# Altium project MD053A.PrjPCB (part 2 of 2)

## Sheet MD053A_POWER_AND_CONNECTORS.SchDoc
size 431 x 279 mm; Date: Not shown in title block; ApprovedBy: Not shown in title block; CheckedBy: Not shown in title block; Author: Not shown in title block; CompanyName: Not shown in title block; Engineer: Not shown in title block; Organization: Not shown in title block; Address1: Not shown in title block; Address2: Not shown in title block; Address3: Not shown in title block; Address4: Not shown in title block; DocumentNumber: 4; Revision: Use project parameter SCH_Rev; SheetNumber: 4; SheetTotal: 5; PageSetup: Record=PageOptions¦CenterHorizontal=True¦CenterVertical=True¦PrintScale=1.00¦XCorrection=1.00¦YCorrection=1.00¦PrintKind=0¦BorderSize=5000000¦LeftOffset=0¦BottomOffset=0¦Orientation=2¦PaperLength=1000¦PaperWidth=1000¦Scale=100¦PaperSource=15¦PrintQuality=600¦MediaType=1¦DitherType=10¦PaperKind=Letter¦PrintScaleMode=1
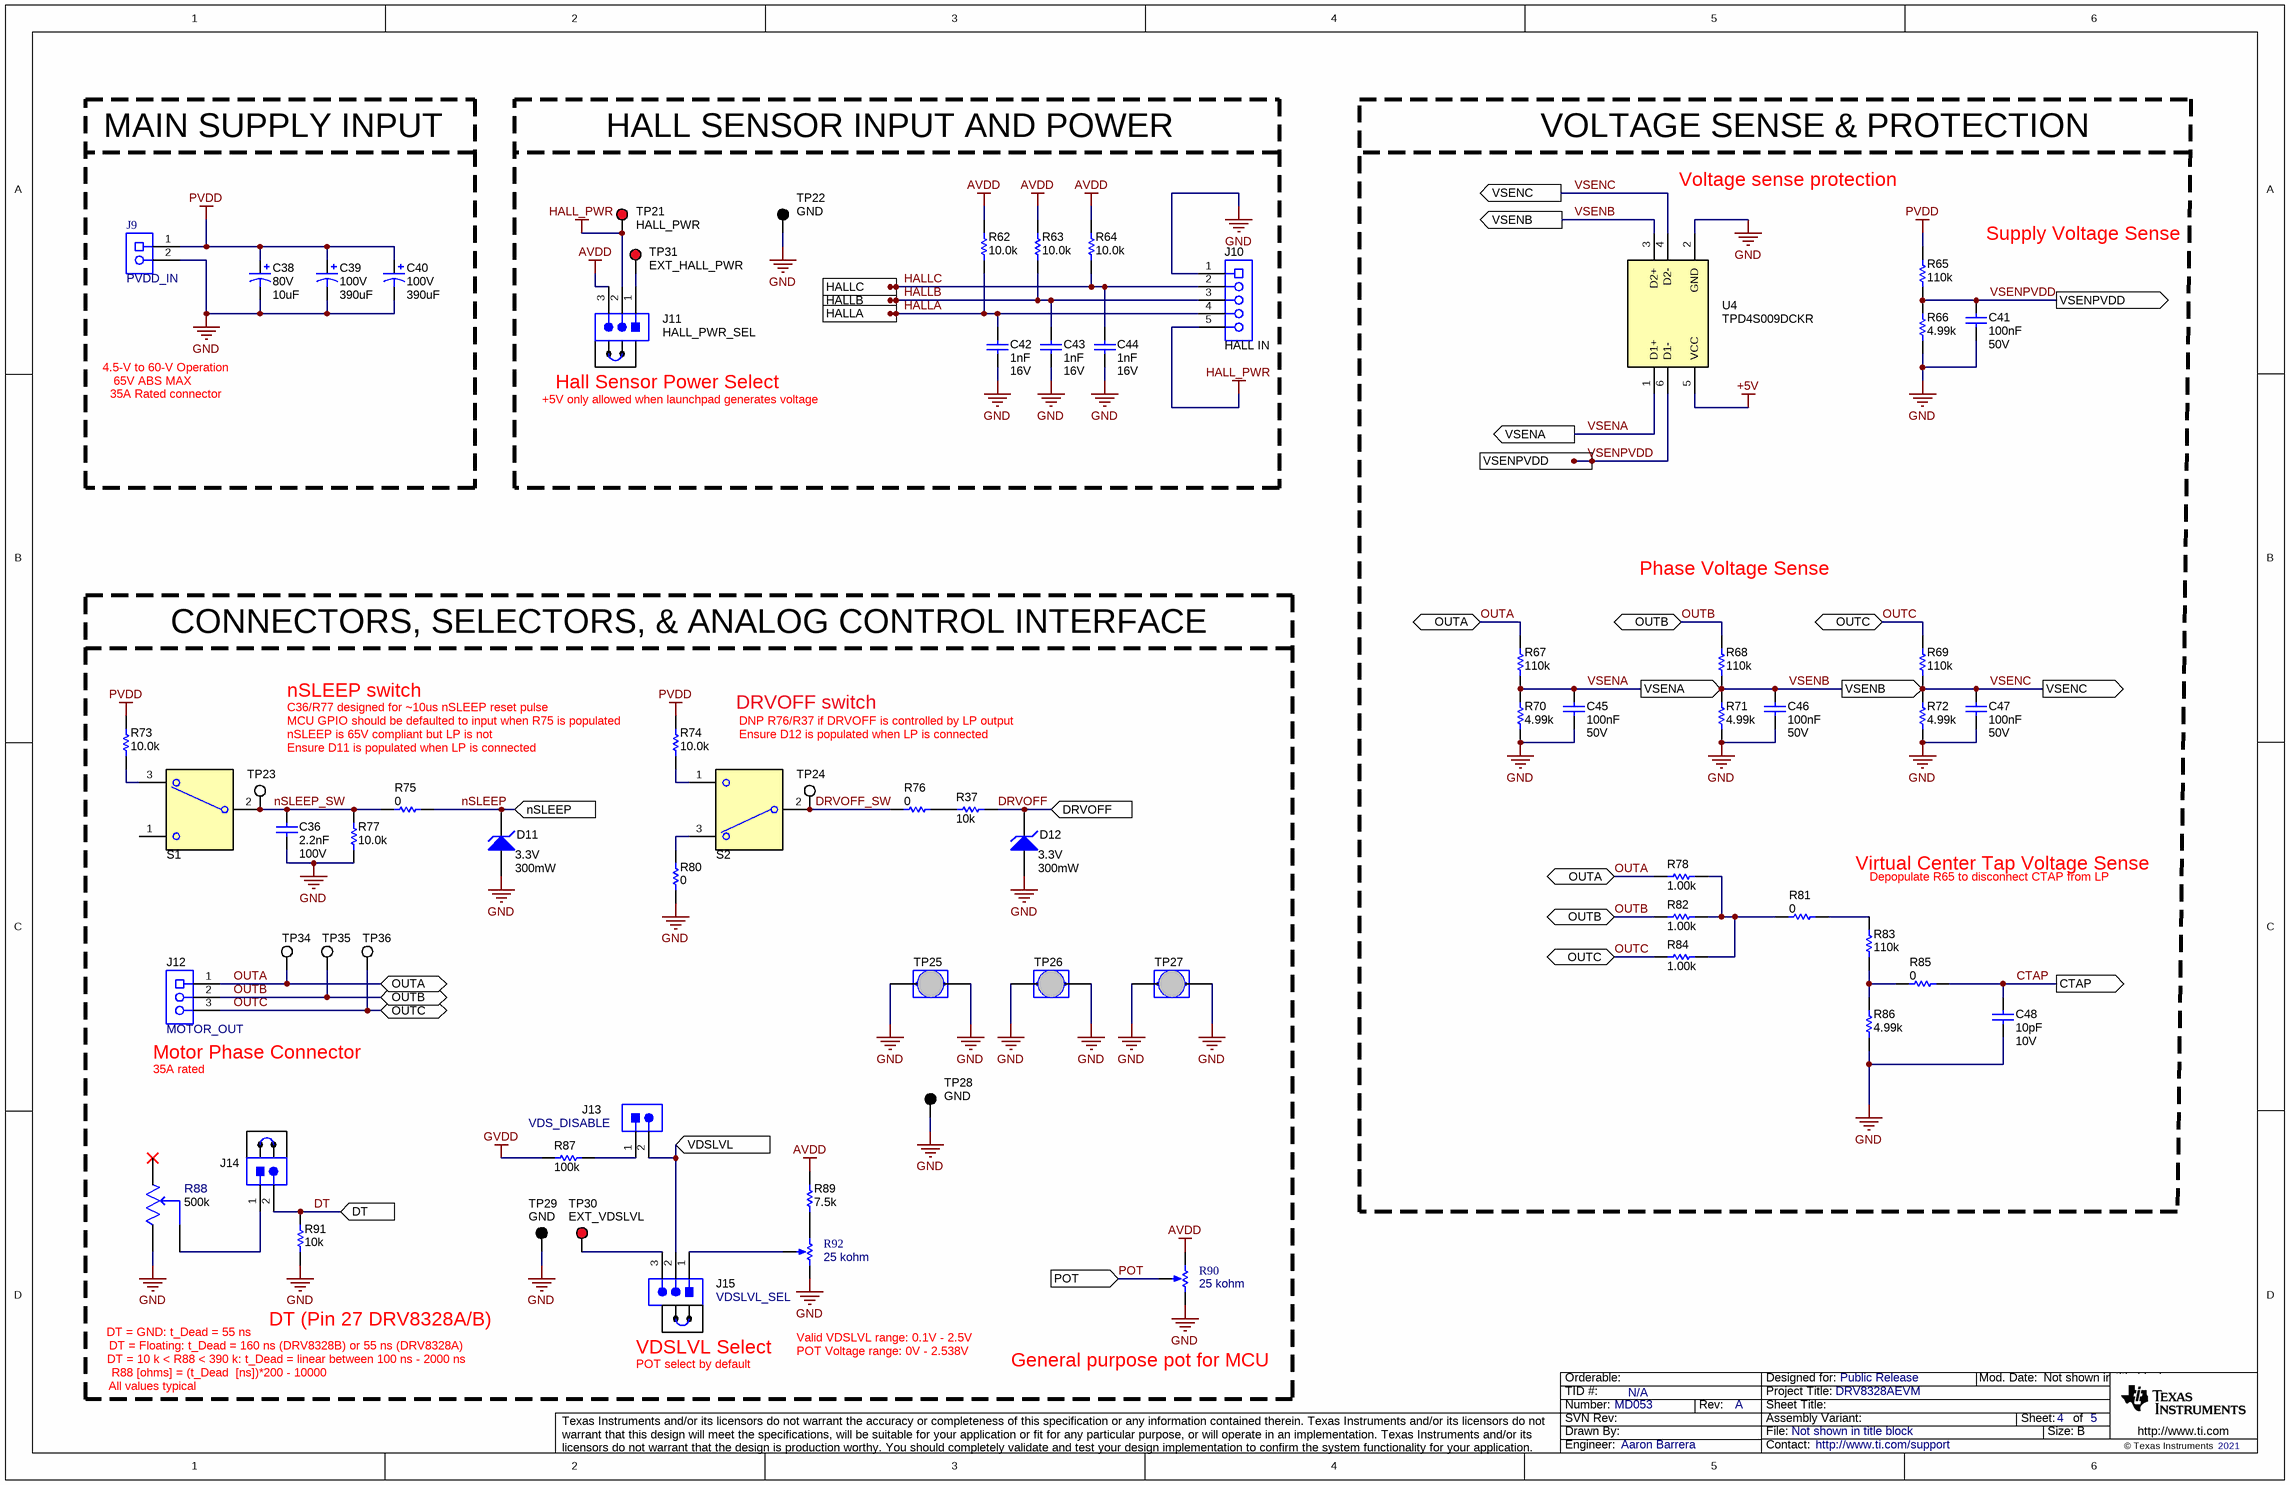
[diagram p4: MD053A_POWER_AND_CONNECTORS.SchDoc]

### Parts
C36  Cap_F: 2.2nF  VDC_V: 100V  [0603L]  (hidden comment: GRM188R72A222KA01D)
C38  VDC_V: 80V  ValueDisplayed: 10uF  [CAPSMT_62_F80]  (hidden comment: EMZA800ADA100MF80G)
C39  VDC_V: 100V  ValueDisplayed: 390uF  [KYB_1250x3500]  (hidden comment: EKYB101ELL391MK35S)
C40  VDC_V: 100V  ValueDisplayed: 390uF  [KYB_1250x3500]  (hidden comment: EKYB101ELL391MK35S)
C41  Cap_F: 100nF  VDC_V: 50V  [0603L]  (hidden comment: 06035C104JAT2A)
C42  Cap_F: 1nF  VDC_V: 16V  [0603L]  (hidden comment: 885012206034)
C43  Cap_F: 1nF  VDC_V: 16V  [0603L]  (hidden comment: 885012206034)
C44  Cap_F: 1nF  VDC_V: 16V  [0603L]  (hidden comment: 885012206034)
C45  Cap_F: 100nF  VDC_V: 50V  [0603L]  (hidden comment: 06035C104JAT2A)
C46  Cap_F: 100nF  VDC_V: 50V  [0603L]  (hidden comment: 06035C104JAT2A)
C47  Cap_F: 100nF  VDC_V: 50V  [0603L]  (hidden comment: 06035C104JAT2A)
C48  Cap_F: 10pF  VDC_V: 10V  [0603L]  (hidden comment: 0603ZC100KAT2A)
D11  value 3.3V  Power_W: 300mW  [SOD-323]  (hidden comment: SZMM3Z3V3ST1G)
D12  value 3.3V  Power_W: 300mW  [SOD-323]  (hidden comment: SZMM3Z3V3ST1G)
J9  PVDD_IN  [Phoenix_1902547]
J10  HALL IN  [Phoenix_1792892]
J11  HALL_PWR_SEL  [FCI_68001-403HLF]
J12  MOTOR_OUT  [Phoenix_1904150]
J13  VDS_DISABLE  [TSW-102-07-G-S]
J14  TSW-102-07-G-S  [TSW-102-07-G-S]  (value not drawn)
J15  VDSLVL_SEL  [FCI_68001-403HLF]
R37  ValueDisplayed: 10k  [0603L]  (hidden comment: CRCW060310K0JNEA)
R62  ValueDisplayed: 10.0k  [TNPW0603]  (hidden comment: TNPW060310K0BEEA)
R63  ValueDisplayed: 10.0k  [TNPW0603]  (hidden comment: TNPW060310K0BEEA)
R64  ValueDisplayed: 10.0k  [TNPW0603]  (hidden comment: TNPW060310K0BEEA)
R65  ValueDisplayed: 110k  [0603L]  (hidden comment: CRCW0603110KFKEA)
R66  ValueDisplayed: 4.99k  [0603L]  (hidden comment: CRCW06034K99FKEA)
R67  ValueDisplayed: 110k  [0603L]  (hidden comment: CRCW0603110KFKEA)
R68  ValueDisplayed: 110k  [0603L]  (hidden comment: CRCW0603110KFKEA)
R69  ValueDisplayed: 110k  [0603L]  (hidden comment: CRCW0603110KFKEA)
R70  ValueDisplayed: 4.99k  [0603L]  (hidden comment: CRCW06034K99FKEA)
R71  ValueDisplayed: 4.99k  [0603L]  (hidden comment: CRCW06034K99FKEA)
R72  ValueDisplayed: 4.99k  [0603L]  (hidden comment: CRCW06034K99FKEA)
R73  ValueDisplayed: 10.0k  [0603L]  (hidden comment: ERA-3ARW103V)
R74  ValueDisplayed: 10.0k  [0603L]  (hidden comment: ERA-3ARW103V)
R75  ValueDisplayed: 0  [0603L]  (hidden comment: ERJ-3GEY0R00V)
R76  ValueDisplayed: 0  [0603L]  (hidden comment: ERJ-3GEY0R00V)
R77  ValueDisplayed: 10.0k  [0603L]  (hidden comment: ERA-3ARW103V)
R78  ValueDisplayed: 1.00k  [0805L]  (hidden comment: RP73PF2A1K0BTDF)
R80  ValueDisplayed: 0  [0603L]  (hidden comment: ERJ-3GEY0R00V)
R81  ValueDisplayed: 0  [0603L]  (hidden comment: ERJ-3GEY0R00V)
R82  ValueDisplayed: 1.00k  [0805L]  (hidden comment: RP73PF2A1K0BTDF)
R83  ValueDisplayed: 110k  [0603L]  (hidden comment: CRCW0603110KFKEA)
R84  ValueDisplayed: 1.00k  [0805L]  (hidden comment: RP73PF2A1K0BTDF)
R85  ValueDisplayed: 0  [0603L]  (hidden comment: ERJ-3GEY0R00V)
R86  ValueDisplayed: 4.99k  [0603L]  (hidden comment: CRCW06034K99FKEA)
R87  ValueDisplayed: 100k  [0603L]  (hidden comment: CRCW0603100KJNEA)
R88  Res_ohm: 500k  [FP-3296W-1-504LF_PTH_Potentiometer_9MM53_4MM83-MFG]  (hidden comment: 3296W-1-504LF)
R89  ValueDisplayed: 7.5k  [0603L]  (hidden comment: RC0603JR-077K5L)
R90  value 25 kohm  [Bourns_3352T]  (hidden comment: 3352T-1-253LF)
R91  ValueDisplayed: 10k  [0603L]  (hidden comment: CRCW060310K0JNEA)
R92  value 25 kohm  [Bourns_3352T]  (hidden comment: 3352T-1-253LF)
S1  nSLEEP_SW  [SW_B12AP]  (value not drawn)
S2  DRVOFF_SW  [SW_B12AP]  (value not drawn)
SH-J6  SNT-100-BK-G  [SNT-100-BK-G]  (value not drawn)
SH-J7  SNT-100-BK-G  [SNT-100-BK-G]  (value not drawn)
SH-J8  SNT-100-BK-G  [SNT-100-BK-G]  (value not drawn)
TP21  HALL_PWR  [Keystone5000]
TP22  GND  [Keystone5001]
TP23  nSLEEP_SW  [Testpoint_Keystone_Miniature]  (value not drawn)
TP24  INHA  [Testpoint_Keystone_Miniature]  (value not drawn)
TP25  GND  [Harwin_D3082-05]  (value not drawn)
TP26  GND  [Harwin_D3082-05]  (value not drawn)
TP27  GND  [Harwin_D3082-05]  (value not drawn)
TP28  GND  [Keystone5001]
TP29  GND  [Keystone5001]
TP30  EXT_VDSLVL  [Keystone5000]
TP31  EXT_HALL_PWR  [Keystone5000]
TP34  OUTA  [Testpoint_Keystone_Compact]  (value not drawn)
TP35  OUTA  [Testpoint_Keystone_Compact]  (value not drawn)
TP36  OUTA  [Testpoint_Keystone_Compact]  (value not drawn)
U4  TPD4S009DCKR  [DCK0006A_N]

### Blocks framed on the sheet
MAIN SUPPLY INPUT: C38-C40 J9
HALL SENSOR INPUT AND POWER: C42-C44 J10 J11 R62-R64 SH-J6 TP21 TP22 TP31
VOLTAGE SENSE & PROTECTION: C41 C45-C48 R65-R72 R78 R81-R86 U4
CONNECTORS, SELECTORS, & ANALOG CONTROL INTERFACE: C36 D11 D12 J12-J15 R37 R73-R77 R80 R87-R92 S1 S2 SH-J7 SH-J8 TP23-TP30 TP34-TP36

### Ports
CTAP (out), DRVOFF (in), DT (in), HALLA (out), HALLB (out), HALLC (out), nSLEEP (in), OUTA (bidir), OUTB (bidir), OUTC (bidir), POT (in), VDSLVL (in), VSENA (out), VSENB (out), VSENC (out), VSENPVDD (out)

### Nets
+5V: U4.5(VCC)
AVDD: J11.3 R62.2 R63.2 R64.2 R89.2 R90.1(CCW)
GND: C36.2 C38.2(-) C39.2(-) C40.2(-) C41.2 C42.2 C43.2 C44.2 C45.1 C46.2 C47.2 C48.2 D11.2(A) D12.2(A) J9.2 J10.1 R66.1 R70.1 R71.1 R72.1 R77.1 R80.1 R86.1 R88.1(CCW) R90.3(CW) R91.1 R92.3(CW) TP22.1 TP25.1 TP25.2 TP26.1 TP26.2 TP27.1 TP27.2 TP28.1 TP29.1 U4.2(GND)
GVDD: R87.1
HALL_PWR: J10.5 J11.2 TP21.1
PVDD: C38.1(+) C39.1(+) C40.1(+) J9.1 R65.2 R73.2 R74.2
CTAP: C48.1 R85.2 ; port CTAP
DRVOFF: D12.1(K) R37.1 ; port DRVOFF
DRVOFF_SW: R76.1 S2.2(COM) TP24.1
DT: J14.2 R91.2 ; port DT
HALLA: C42.1 J10.4 R62.1 ; port HALLA
HALLB: C43.1 J10.3 R63.1 ; port HALLB
HALLC: C44.1 J10.2 R64.1 ; port HALLC
nSLEEP: D11.1(K) R75.2 ; port nSLEEP
nSLEEP_SW: C36.1 R75.1 R77.2 S1.2(COM) TP23.1
OUTA: J12.1 R67.2 R78.1 TP34.1 ; port OUTA
OUTB: J12.2 R68.2 R82.1 TP35.1 ; port OUTB
OUTC: J12.3 R69.2 R84.1 TP36.1 ; port OUTC
POT: R90.2(WIPER) ; port POT
VDSLVL: J13.2 J15.2 ; port VDSLVL
VSENA: C45.2 R67.1 R70.2 U4.1(D1+) ; port VSENA
VSENB: C46.1 R68.1 R71.2 U4.3(D2+) ; port VSENB
VSENC: C47.1 R69.1 R72.2 U4.4(D2-) ; port VSENC
VSENPVDD: C41.1 R65.1 R66.2 U4.6(D1-) ; port VSENPVDD
NetJ11_1: J11.1 TP31.1
NetJ13_1: J13.1 R87.2
NetJ14_1: J14.1 R88.2(WIPER)
NetJ15_1: J15.1 R92.2(WIPER)
NetJ15_3: J15.3 TP30.1
NetR37_2: R37.2 R76.2
NetR73_1: R73.1 S1.3
NetR74_1: R74.1 S2.1
NetR78_2: R78.2 R81.1 R82.2 R84.2
NetR80_2: R80.2 S2.3
NetR81_2: R81.2 R83.2
NetR83_1: R83.1 R85.1 R86.2
NetR89_1: R89.1 R92.1(CCW)

Not connected (* = marked no-connect by the designer): R88 3(CW)*; S1 1

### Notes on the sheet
- Voltage sense protection
- Supply Voltage Sense
- 4.5-V to 60-V Operation
- 65V ABS MAX
- 35A Rated connector
- (near SH-J6) +5V only allowed when launchpad generates voltage
- (near SH-J6) Hall Sensor Power Select
- Phase Voltage Sense
- nSLEEP switch
- DRVOFF switch
- C36/R77 designed for
  0us nSLEEP reset pulse
- (near R74) MCU GPIO should be defaulted to input when R75 is populated
- nSLEEP is 65V compliant but LP is not
- Ensure D11 is populated when LP is connected
- Ensure D12 is populated when LP is connected
- DNP R76/R37 if DRVOFF is controlled by LP output
- Depopulate R65 to disconnect CTAP from LP
- Virtual Center Tap Voltage Sense
- (near J12) Motor Phase Connector
- 35A rated
- DT = GND: t_Dead = 55 ns
- R88 [ohms] = (t_Dead  [ns])*200 - 10000
- DT = 10 k < R88 < 390 k: t_Dead = linear between 100 ns - 2000 ns
- DT = Floating: t_Dead = 160 ns (DRV8328B) or 55 ns (DRV8328A)
- DT (Pin 27 DRV8328A/B)
- (near SH-J8) VDSLVL Select
- (near SH-J8) POT select by default
- Valid VDSLVL range: 0.1V - 2.5V
- POT Voltage range: 0V - 2.538V
- General purpose pot for MCU
- All values typical

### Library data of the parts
C36 = CMP-0007475-4: CAP, CERM, 2200 pF, 100 V, +/- 10%, X7R, 0603; Manufacturer: MuRata; TaMin_C: -55°C; Polarized: N; SizeAreaWB_mm2: 4.68; Value1: Unknown; U/M: EA; Value: 2200pF; TaMax_C: 125°C; SizeZ_mm: 1; SizeX_mm: 1.6; SizeY_mm: 0.8; Cap_Case: 0603; SizeArea_mm2: 1.28; AEC Category: Q200
C38 = CMP-0011397-2: CAP, AL, 10 uF, 80 V, +/- 20%, 2.4 ohm, SMD; Manufacturer: Chemi-Con; TaMin_C: -55°C; ESR_ohm: 2.4; Polarized: Y; SizeAreaWB_mm2: 73.96; Value1: 2.4 ohm; U/M: EA; Value: 10uF; TaMax_C: 105°C; SizeZ_mm: 7.7; SizeX_mm: 6.6; Cap_Case: F80; SizeArea_mm2: 43.56; CompType: Capacitor; Cap_F: 10µF; IRMS_A: 60mA; AEC Category: Q200
C39 C40 = CMP-0009875-2: CAP, AL, 390 uF, 100 V, +/- 20%, 0.026 ohm, TH; Manufacturer: Chemi-Con; TaMin_C: -40°C; ESR_ohm: 0.026; Polarized: Y; SizeAreaWB_mm2: 210.25; U/M: EA; Value: 390uF; TaMax_C: 105°C; SizeZ_mm: 36.5; SizeX_mm: 12.5; Cap_Case: 12.5x35mm; SizeArea_mm2: 156.25; CompType: Capacitor; AEC Qualified: N; Cap_F: 390µF; IRMS_A: 2.25A; AEC Category: Q200
C41 C45-C47 = CMP-0083854-1: CAP, CERM, 0.1 µF, 50 V,+/- 5%, X7R, 0603; Manufacturer: AVX; TaMin_C: -55°C; Polarized: N; Green_Lifecycle: Active; SizeAreaWB_mm2: 4.68; Green_REACh: Passed; U/M: EA; Value: 0.1uF; TaMax_C: 125°C; SizeZ_mm: 1; SizeX_mm: 1.6; SizeY_mm: 0.8; Cap_Case: 0603; SizeArea_mm2: 1.28; AEC Category: Q200; ValueDisplayed: 0.1µF
C42-C44 = CMP-0006826-4: CAP, CERM, 1000 pF, 16 V, +/- 10%, X7R, 0603; Manufacturer: Wurth Elektronik; TaMin_C: -55°C; Polarized: N; SizeAreaWB_mm2: 4.68; Value1: Unknown; U/M: EA; Value: 1000pF; TaMax_C: 125°C; SizeZ_mm: 1; SizeX_mm: 1.6; SizeY_mm: 0.8; Cap_Case: 0603; SizeArea_mm2: 1.28; AEC Category: Q200
C48 = CMP-0006811-4: CAP, CERM, 10 pF, 10 V, +/- 10%, X7R, 0603; Manufacturer: AVX; TaMin_C: -55°C; Polarized: N; SizeAreaWB_mm2: 4.68; Value1: Unknown; U/M: EA; Value: 10pF; TaMax_C: 125°C; SizeZ_mm: 1; SizeX_mm: 1.6; SizeY_mm: 0.8; Cap_Case: 0603; SizeArea_mm2: 1.28; AEC Category: Q200
D11 D12 = CMP-0085730-1: Diode, Zener, 3.3 V, 300 mW, AEC-Q101, SOD-323; Manufacturer: ON Semiconductor; RJA_CperW: 416; AEC Qualified: Y; SizeArea_mm2: 3.645; SizeX_mm: 2.7; SizeY_mm: 1.35; SizeZ_mm: 1; AEC Category: Q101; SizeAreaWB_mm2: 8.695; Value1: 0.3W
J9 = CMP-0055527-1: Terminal Block, 9.52mm, 2x1, R/A, TH; Manufacturer: Phoenix Contact; PartNumber: 1902547; Cert_VDE: Y; CNHeader: FALSE; Current_A: 32A; Gender: Female; Voltage_V: 1kV; Row_Count: 1; Pitch_mm: 9.52; CT: TRUE
J10 = CMP-0055532-1: Terminal Block, 5mm, 5x1, R/A, TH; Manufacturer: Phoenix Contact; PartNumber: 1792892; Cert_VDE: Y; CNHeader: FALSE; Current_A: 16A; Gender: Female; Voltage_V: 400V; Row_Count: 1; Pitch_mm: 5; CT: TRUE
J11 J15 = CMP-0065026-1: Header, 2.54mm, 3x1, Tin, TH; Manufacturer: FCI; PartNumber: 68001-403HLF; CNHeader: True; Current_A: 3A; Shrouded: N; Gender: Male; Cert_CSA: Y; Voltage_V: 1.5kV; Row_Count: 1; Pitch_mm: 2.54; CT: False
J12 = CMP-0055528-1: Terminal Block, 9.52mm, 3x1, R/A, TH; Manufacturer: Phoenix Contact; PartNumber: 1904150; Cert_VDE: Y; CNHeader: FALSE; Current_A: 32A; Gender: Female; Voltage_V: 1kV; Row_Count: 1; Pitch_mm: 9.52; CT: TRUE
J13 J14 = CMP-0075405-3: Header, 100mil, 2x1, Gold, TH; Manufacturer: Samtec; Current_A: 6.3A; Green_Lifecycle: Active; Pitch_mm: 2.54; Cert_CSA: Y; Cert_VDE: N; Green_REACh: Passed; Row_Count: 1; Gender: Male; Voltage_V: 550V
R37 = CMP-0025701-2: RES, 10 k, 5%, 0.1 W, 0603; Manufacturer: Vishay-Dale; Power_W: 100mW; TempCo: 200 ppm/C; Value_Code: 10k0; U/M: EA; Value: 10k; EIA_Code: E24; SizeX_mm: 1.6; SizeY_mm: 0.8; SizeZ_mm: 1; Value2: 0.1W; SizeArea_mm2: 1.28; VDC_V: 75V; AEC Category: Q200
R62-R64 = CMP-0025686-1: RES, 10.0 k, 0.1%, 0.1 W, AEC-Q200 Grade 1, 0603; Manufacturer: Vishay-Dale; Power_W: 100mW; TempCo: 25 ppm/C; Value_Code: 10k0; U/M: EA; Value: 10.0k; EIA_Code: E192; Res_ohm: 10k; SizeX_mm: 1.6; SizeY_mm: 0.85; SizeZ_mm: 0.55; Value2: 0.1W; SizeArea_mm2: 1.36; AEC Qualified: Y; VDC_V: 75V; AEC Grade: 1; AEC Category: Q200
R65 R67-R69 R83 = CMP-0022008-4: RES, 110 k, 1%, 0.1 W, AEC-Q200 Grade 0, 0603; Manufacturer: Vishay-Dale; Power_W: 100mW; TempCo: 100 ppm/C; Value: 110k; EIA_Code: E96; SizeX_mm: 1.6; SizeY_mm: 0.8; SizeZ_mm: 1; Value2: 0.1W; SizeArea_mm2: 1.28; AEC Qualified: Y; VDC_V: 75V; AEC Category: Q200; AEC Grade: 0
R66 R70-R72 R86 = CMP-0022458-4: RES, 4.99 k, 1%, 0.1 W, AEC-Q200 Grade 0, 0603; Manufacturer: Vishay-Dale; Power_W: 100mW; TempCo: 100 ppm/C; Value_Code: 4k99; Value: 4.99k; EIA_Code: E96; SizeX_mm: 1.6; SizeY_mm: 0.8; SizeZ_mm: 1; Value2: 0.1W; SizeArea_mm2: 1.28; AEC Qualified: Y; VDC_V: 75V; AEC Category: Q200; AEC Grade: 0
R73 R74 R77 = CMP-0086251-1: RES, 10.0 k, 0.05%, 0.1 W, AEC-Q200 Grade 0, 0603; Manufacturer: Panasonic; Res_ohm: 10k; Value: 10.0k; SizeY_mm: 0.8; SizeArea_mm2: 1.28; SizeAreaWB_mm2: 4.68; AEC Grade: 0; Power_W: 100mW; SizeX_mm: 1.6; Value2: 0.1W; Value_Code: 10k0; SizeZ_mm: 1; AEC Qualified: Y; AEC Category: Q200; TempCo: 10 ppm/C
R75 R76 R80 R81 R85 = CMP-0025874-4: RES, 0, 5%, 0.1 W, AEC-Q200 Grade 0, 0603; Manufacturer: Panasonic; Power_W: 100mW; TempCo: 600 ppm/C; Value_Code: 0000; Value: 0; EIA_Code: E24; SizeX_mm: 1.6; SizeY_mm: 0.8; SizeZ_mm: 1; Value2: 0.1W; SizeArea_mm2: 1.28; AEC Qualified: Y; VDC_V: 50V; AEC Category: Q200; SizeAreaWB_mm2: 4.68
R78 R82 R84 = CMP-0019089-2: RES, 1.00 k, 0.1%, 0.25 W, 0805; Manufacturer: TE Connectivity; Power_W: 250mW; TempCo: 25 ppm/C; Value_Code: 1k00; U/M: EA; Value: 1.00k; EIA_Code: E192; Res_ohm: 1k; SizeX_mm: 2; SizeY_mm: 1.25; SizeZ_mm: 1.45; Value2: 0.25W; SizeArea_mm2: 2.5; CompType: Resistor; VDC_V: 150V; AEC Category: Q200
R87 = CMP-0025698-4: RES, 100 k, 5%, 0.1 W, AEC-Q200 Grade 0, 0603; Manufacturer: Vishay-Dale; Power_W: 100mW; TempCo: 200 ppm/C; Value: 100k; EIA_Code: E24; SizeX_mm: 1.6; SizeY_mm: 0.8; SizeZ_mm: 1; Value2: 0.1W; SizeArea_mm2: 1.28; AEC Qualified: Y; VDC_V: 75V; AEC Category: Q200; AEC Grade: 0
R88 = CMP-0088033-1: 500 kOhms 0.5W, 1/2W PC Pins Through Hole Trimmer Potentiometer Cermet 25 Turn Top Adjustment; Manufacturer: Bourns; SizeZ_mm: 12.05mm; Power_W: 500mW; VDC_V: 300V; TempCo: 100ppm/°C; Tolerance_%: 10%; AEC Qualified: No
R89 = CMP-0025940-5: RES, 7.5 k, 5%, 0.1 W, 0603; Manufacturer: Yageo; Power_W: 100mW; TempCo: 100 ppm/C; Value_Code: 7k50; Value: 7.5k; EIA_Code: E24; SizeX_mm: 1.6; SizeY_mm: 0.8; SizeZ_mm: 1; Value2: 0.1W; SizeArea_mm2: 1.28; AEC Qualified: N; VDC_V: 75V; AEC Category: Q200; SizeAreaWB_mm2: 4.68
R90 R92 = CMP-0001776-2: Trimmer Potentiometer, 25kohm, 0.5W, TH; Manufacturer: Bourns
R91 = CMP-0025701-3: RES, 10 k, 5%, 0.1 W, 0603; Manufacturer: Vishay-Dale; Power_W: 100mW; TempCo: 200 ppm/C; Value_Code: 10k0; U/M: EA; Value: 10k; EIA_Code: E24; SizeX_mm: 1.6; SizeY_mm: 0.8; SizeZ_mm: 1; Value2: 0.1W; SizeArea_mm2: 1.28; VDC_V: 75V; AEC Category: Q200
S1 S2 = CMP-0002155-2: SWITCH TOGGLE SPDT 0.4VA 28V; PartNumber: B12AP; Manufacturer: NKK Switches; SwitchFunction: On-On; PositionCount: 2; CurrentRating_mA: 100A
SH-J6-SH-J8 = CMP-0003623-3: Shunt, 100mil, Gold plated, Black; Alternate PartNumber: 969102-0000-DA; Manufacturer: Samtec; Alternate Manufacturer: 3M; Value: 1x2
TP21 TP30 TP31 = CMP-0055137-1: Test Point, Miniature, Red, TH; PartNumber: 5000; Manufacturer: Keystone; ContactFinish: Silver; CNHeader: FALSE; CT: TRUE; Green_Lifecycle: Active; Green_REACh: Passed
TP22 TP28 TP29 = CMP-0055138-1: Test Point, Miniature, Black, TH; Manufacturer: Keystone; CNHeader: FALSE; Green_Lifecycle: Active; Green_REACh: Passed; ContactFinish: Silver; CT: TRUE
TP23 TP24 = CMP-0055152-1: Test Point, Miniature, SMT; Manufacturer: Keystone; CNHeader: FALSE; Green_Lifecycle: Active; Green_REACh: Passed; CT: TRUE
TP25-TP27 = CMP-0075110-1: 1mm Uninsulated Shorting Plug, 10.16mm spacing, TH; Manufacturer: Harwin; PartNumber: D3082-05; CNHeader: False; Green_Lifecycle: Active; Green_REACh: Passed; CompType: Jumper Wire
TP34-TP36 = CMP-0055153-1: Test Point, Compact, SMT; Manufacturer: Keystone; CNHeader: FALSE; Green_Lifecycle: Active; Green_REACh: Passed; CT: TRUE
U4 = CMP-0043118-3: 4-Channel ESD Solution for High-Speed Differential Interface, DCK0006A (SOT-SC70-6); Manufacturer: Texas Instruments; IO Leakage Current(nA): 10; IO Capacitance(Typ)(pF): 0.8; Eco-Plan: Green (RoHS & no Sb/Br); Breakdown Voltage(Min)(V): 9; Differential Capacitance(pF): 0.05; AEC Category: Q200; AEC Qualified: N; CompType: IC; Rating: Catalog; SizeAreaWB_mm2: 9.3; SizeArea_mm2: 4.2; SizeX_mm: 2.1; SizeY_mm: 2.0; SizeZ_mm: 1.1

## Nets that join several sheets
+5V: MD053A_DRIVER (R30.2 TP14.1), MD053A_POWER_AND_CONNECTORS (U4.5)
AVDD: MD053A_DRIVER (8 pins), MD053A_FETS_AND_POWER_STAGE (C29.1 U2.5), MD053A_LDO (J16.2), MD053A_POWER_AND_CONNECTORS (6 pins)
GND: MD053A_DRIVER (16 pins), MD053A_FETS_AND_POWER_STAGE (10 pins), MD053A_LDO (8 pins), MD053A_POWER_AND_CONNECTORS (37 pins)
GVDD: MD053A_DRIVER (C7.1 TP12.1 U1.4), MD053A_POWER_AND_CONNECTORS (R87.1)
LSS: MD053A_DRIVER (J5.14 TP3.1 U1.17), MD053A_FETS_AND_POWER_STAGE (14 pins)
PVDD: MD053A_DRIVER (5 pins), MD053A_FETS_AND_POWER_STAGE (12 pins), MD053A_LDO (C33.1 C34.1 J8.2 U3.8), MD053A_POWER_AND_CONNECTORS (7 pins)
CTAP: MD053A_DRIVER (J6.11 R32.2), MD053A_POWER_AND_CONNECTORS (C48.1 R85.2)
DRVOFF: MD053A_DRIVER (J7.16 R6.1 TP1.1), MD053A_POWER_AND_CONNECTORS (D12.1 R37.1)
DT: MD053A_DRIVER (R20.1), MD053A_POWER_AND_CONNECTORS (J14.2 R91.2)
GHA: MD053A_DRIVER (J5.4 U1.7), MD053A_FETS_AND_POWER_STAGE (R43.1 R46.1)
GHB: MD053A_DRIVER (J5.8 U1.11), MD053A_FETS_AND_POWER_STAGE (R44.1 R47.1)
GHC: MD053A_DRIVER (J5.12 U1.15), MD053A_FETS_AND_POWER_STAGE (R45.1 R48.1)
GLA: MD053A_DRIVER (J5.5 U1.8), MD053A_FETS_AND_POWER_STAGE (R49.1 R52.1)
GLB: MD053A_DRIVER (J5.9 U1.12), MD053A_FETS_AND_POWER_STAGE (R50.1 R53.1)
GLC: MD053A_DRIVER (J5.13 U1.16), MD053A_FETS_AND_POWER_STAGE (R51.1 R54.1)
HALLA: MD053A_DRIVER (J7.13), MD053A_POWER_AND_CONNECTORS (C42.1 J10.4 R62.1)
HALLB: MD053A_DRIVER (J7.18), MD053A_POWER_AND_CONNECTORS (C43.1 J10.3 R63.1)
HALLC: MD053A_DRIVER (J7.20), MD053A_POWER_AND_CONNECTORS (C44.1 J10.2 R64.1)
ISENA: MD053A_DRIVER (J6.16), MD053A_FETS_AND_POWER_STAGE (C31.1 R59.1)
nSLEEP: MD053A_DRIVER (5 pins), MD053A_POWER_AND_CONNECTORS (D11.1 R75.2)
OUTA: MD053A_FETS_AND_POWER_STAGE (6 pins), MD053A_POWER_AND_CONNECTORS (J12.1 R67.2 R78.1 TP34.1)
OUTB: MD053A_FETS_AND_POWER_STAGE (6 pins), MD053A_POWER_AND_CONNECTORS (J12.2 R68.2 R82.1 TP35.1)
OUTC: MD053A_FETS_AND_POWER_STAGE (6 pins), MD053A_POWER_AND_CONNECTORS (J12.3 R69.2 R84.1 TP36.1)
POT: MD053A_DRIVER (R34.1 R39.1), MD053A_POWER_AND_CONNECTORS (R90.2)
SHA: MD053A_DRIVER (C3.2 J5.3 U1.6), MD053A_FETS_AND_POWER_STAGE (NT1.1)
SHB: MD053A_DRIVER (C8.2 J5.7 U1.10), MD053A_FETS_AND_POWER_STAGE (NT2.1)
SHC: MD053A_DRIVER (C9.2 J5.11 U1.14), MD053A_FETS_AND_POWER_STAGE (NT3.1)
VDSLVL: MD053A_DRIVER (R21.1 R28.2), MD053A_POWER_AND_CONNECTORS (J13.2 J15.2)
VSENA: MD053A_DRIVER (J6.6), MD053A_POWER_AND_CONNECTORS (C45.2 R67.1 R70.2 U4.1)
VSENB: MD053A_DRIVER (J6.8), MD053A_POWER_AND_CONNECTORS (C46.1 R68.1 R71.2 U4.3)
VSENC: MD053A_DRIVER (J6.10), MD053A_POWER_AND_CONNECTORS (C47.1 R69.1 R72.2 U4.4)
VSENPVDD: MD053A_DRIVER (J6.12), MD053A_POWER_AND_CONNECTORS (C41.1 R65.1 R66.2 U4.6)

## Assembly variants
001: not fitted C1 C10 C11 C12 C13 C15 C17 C22 C23 C24 C25 C26 C27 C28 C30 C32 C48 D5 D6 D7 D8 D9 D10 FID1 FID2 FID3 R1 R2 R3 R4 R5 R6 R7 R8 R9 R10 R16 R27 R28 R32 R33 R34 R35 R36 R40 R41 R42 R46 R47 R48 R52 R53 R54 R55 R56 R57 R75 R78 R81 R82 R83 R84 R85 R86 R91; alternate parts U1 -> CMP-0091885-1
002: not fitted C1 C10 C11 C12 C13 C15 C17 C22 C23 C24 C25 C26 C27 C28 C30 C32 C48 D5 D6 D7 D8 D9 D10 FID1 FID2 FID3 R1 R2 R3 R4 R5 R6 R7 R8 R9 R10 R16 R27 R28 R32 R33 R34 R35 R36 R40 R41 R42 R46 R47 R48 R52 R53 R54 R55 R56 R57 R75 R78 R81 R82 R83 R84 R85 R86 R91; alternate parts U1 -> CMP-0092296-2
003: not fitted C10 C11 C12 C13 C15 C17 C22 C23 C24 C25 C26 C27 C28 C30 C32 C48 C49 D5 D6 D7 D8 D9 D10 FID1 FID2 FID3 R11 R12 R13 R14 R15 R16 R17 R18 R19 R20 R21 R27 R28 R32 R33 R34 R35 R36 R40 R41 R42 R46 R47 R48 R52 R53 R54 R55 R56 R57 R75 R78 R81 R82 R83 R84 R85 R86 R91; alternate parts U1 -> CMP-0092297-2
004: not fitted C10 C11 C12 C13 C15 C17 C22 C23 C24 C25 C26 C27 C28 C30 C32 C48 C49 D5 D6 D7 D8 D9 D10 FID1 FID2 FID3 R11 R12 R13 R14 R15 R16 R17 R18 R19 R20 R21 R27 R28 R32 R33 R34 R35 R36 R40 R41 R42 R46 R47 R48 R52 R53 R54 R55 R56 R57 R75 R78 R81 R82 R83 R84 R85 R86 R91; alternate parts U1 -> CMP-0092298-2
